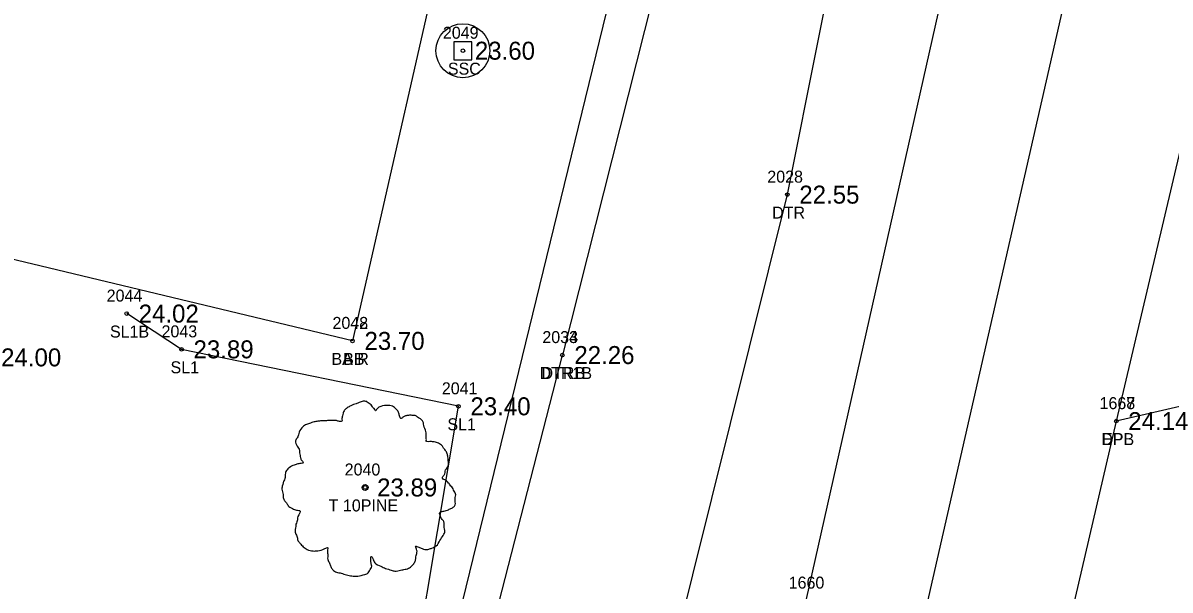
# Model space of a CAD drawing. Extents: x 2654414 to 2656963, y 761776 to 764965.
# Drawn here: x 2655410.2 to 2655506, y 762237.5 to 762284.8 of the extents above; entities that cross this region are included whole.
import ezdxf

# ---------------------------------------------------------------- set-up
doc = ezdxf.new("R2010")
doc.units = 0
for name, color, linetype in [('Default', 7, 'Continuous'), ('RD_EX_Bldg', 7, 'Continuous'), ('RD_EX_Bldg_txCode', 7, 'Continuous'), ('RD_EX_Driveway', 7, 'Continuous'), ('RD_EX_Driveway_txCode', 7, 'Continuous'), ('RD_EX_Fence_Other', 7, 'Continuous'), ('RD_EX_H2O', 7, 'Continuous'), ('RD_EX_H2O_txCode', 7, 'Continuous'), ('RD_EX_Road', 7, 'Continuous'), ('RD_EX_Road_txCode', 7, 'Continuous'), ('RD_EX_TX_Bldg_ELEV', 7, 'Continuous'), ('RD_EX_TX_Conc_ELEV', 7, 'Continuous'), ('RD_EX_TX_Driveway_ELEV', 7, 'Continuous'), ('RD_EX_TX_H2O_ELEV', 7, 'Continuous'), ('RD_EX_TX_Road_ELEV', 7, 'Continuous'), ('RD_EX_TX_UT_ELEV', 7, 'Continuous'), ('RD_EX_TX_VEG_ELEV', 7, 'Continuous'), ('RD_EX_UT', 7, 'Continuous'), ('RD_EX_UT_txCode', 7, 'Continuous'), ('RD_EX_VEG', 7, 'Continuous'), ('RD_EX_VEG_txCode', 7, 'Continuous'), ('RD_HC_Cl', 7, 'Continuous'), ('RD_SMD_Locator', 7, 'Continuous')]:
    doc.layers.add(name, color=color, linetype=linetype)

msp = doc.modelspace()

# ---------------------------------------------------------------- linework, layer by layer
at = {"layer": 'Default'}
msp.add_line((2656050.51, 764712.367), (2655383.263, 761787.511), dxfattribs=at)
at = {"layer": 'RD_EX_Bldg'}
msp.add_lwpolyline([(2655437.715, 762258.295), (2655390.483, 762269.628), (2655398.7, 762307.917), (2655446.539, 762297.096), (2655437.715, 762258.295)], dxfattribs=at)
at = {"layer": 'RD_EX_Driveway'}
msp.add_lwpolyline([(2655508.173, 762280.146), (2655514.751, 762268.051), (2655517.637, 762265.69), (2655514.347, 762252.861), (2655509.918, 762253.548), (2655501.462, 762251.601)], dxfattribs=at)
at = {"layer": 'RD_EX_Fence_Other'}
msp.add_line((2655466.192, 762315.625), (2655445.664, 762231.576), dxfattribs=at)
at = {"layer": 'RD_EX_H2O'}
msp.add_line((2655465.406, 762297.339), (2655455.231, 762257.113), dxfattribs=at)
msp.add_lwpolyline([(2655465.406, 762297.339), (2655472.381, 762299.489), (2655479.157, 762296.474), (2655474.006, 762270.501), (2655462.934, 762226.04), (2655458.028, 762221.446), (2655449.91, 762220.499), (2655446.472, 762222.967), (2655455.231, 762257.113)], dxfattribs=at)
at = {"layer": 'RD_EX_Road'}
for points in [[(2655700.994, 763232.279), (2655693.552, 763198.573), (2655671.649, 763102.037), (2655649.038, 763001.061), (2655627.271, 762906.233), (2655604.996, 762809.365), (2655598.992, 762783.09), (2655583.655, 762714.137), (2655561.97, 762618.323), (2655556.356, 762593.843), (2655548.114, 762557.141), (2655540.102, 762522.478), (2655518.03, 762425.04), (2655496.479, 762329.558), (2655475.552, 762236.625), (2655473.199, 762226.142), (2655466.574, 762197.504), (2655460.058, 762168.164), (2655454.261, 762143.776), (2655432.5, 762049.878), (2655410.7, 761955.515), (2655388.166, 761858.426), (2655373.501, 761793.951)], [(2655670.037, 762995.178), (2655648.569, 762900.673), (2655631.27, 762824.032), (2655626.665, 762802.872), (2655621.781, 762781.907), (2655611.705, 762738.435), (2655604.931, 762708.622), (2655582.644, 762610.543), (2655576.456, 762583.319), (2655561.406, 762517.242), (2655539.154, 762414.805), (2655531.984, 762386.147), (2655517.984, 762324.295), (2655508.173, 762280.146), (2655501.462, 762251.601), (2655496.922, 762232.086), (2655477.204, 762144.974), (2655472.137, 762122.524), (2655453.741, 762045.099), (2655431.791, 761949.924), (2655409.76, 761853.25), (2655401.248, 761816.416), (2655394.612, 761787.366)]]:
    msp.add_lwpolyline(points, dxfattribs=at)
at = {"layer": 'RD_EX_UT'}
for p, q in [((2655447.679, 762283.261), (2655446.178, 762283.262)), ((2655446.178, 762283.262), (2655446.178, 762281.761)), ((2655447.678, 762281.761), (2655447.679, 762283.261)), ((2655446.178, 762281.761), (2655447.678, 762281.761))]:
    msp.add_line(p, q, dxfattribs=at)
msp.add_circle((2655446.928, 762282.511), 2.25, dxfattribs=at)
at = {"layer": 'RD_EX_VEG'}
msp.add_lwpolyline([(2655443.065, 762231.918), (2655446.559, 762252.837), (2655423.447, 762257.591), (2655418.867, 762260.575)], dxfattribs=at)
for centre, radius in [((2655438.769, 762246.065), 0.25), ((2655438.757, 762246.046), 0.0001)]:
    msp.add_circle(centre, radius, dxfattribs=at)
for points in [[(2655438.901, 762253.232), (2655438.601, 762253.257), (2655438.277, 762253.157), (2655438.027, 762253.057), (2655437.802, 762252.982), (2655437.577, 762252.882), (2655437.277, 762252.707), (2655437.052, 762252.507), (2655436.927, 762252.258), (2655436.877, 762252.033), (2655436.827, 762251.758), (2655436.827, 762251.583), (2655436.702, 762251.558), (2655436.552, 762251.583), (2655436.302, 762251.658), (2655436.053, 762251.658), (2655435.803, 762251.658), (2655435.453, 762251.633), (2655435.103, 762251.633), (2655434.828, 762251.583), (2655434.503, 762251.533), (2655434.128, 762251.408), (2655433.779, 762251.283), (2655433.479, 762251.033), (2655433.229, 762250.558), (2655433.104, 762250.208), (2655432.954, 762249.959), (2655433.104, 762249.509), (2655433.279, 762249.159), (2655433.304, 762248.959), (2655433.379, 762248.534), (2655433.479, 762248.309), (2655433.604, 762248.109), (2655433.529, 762248.084), (2655433.154, 762248.034), (2655432.854, 762247.934), (2655432.429, 762247.71), (2655432.204, 762247.485), (2655432.104, 762247.16), (2655432.079, 762246.81), (2655431.979, 762246.61), (2655431.904, 762246.335), (2655431.879, 762246.26), (2655431.829, 762245.935), (2655431.929, 762245.485), (2655431.954, 762245.136), (2655432.079, 762244.911), (2655432.229, 762244.736), (2655432.404, 762244.486), (2655432.804, 762244.261), (2655433.129, 762244.161), (2655433.329, 762244.136), (2655433.154, 762243.636), (2655433.104, 762243.286), (2655432.979, 762242.887), (2655432.979, 762242.812), (2655432.929, 762242.337), (2655433.079, 762242.012), (2655433.154, 762241.637), (2655433.329, 762241.412), (2655433.604, 762241.112), (2655433.928, 762240.888), (2655434.428, 762240.763), (2655434.828, 762240.788), (2655435.403, 762240.962), (2655435.653, 762241.037), (2655435.628, 762240.863), (2655435.653, 762240.488), (2655435.653, 762240.063), (2655435.803, 762239.738), (2655435.903, 762239.463), (2655436.053, 762239.213), (2655436.377, 762238.988), (2655436.777, 762238.913), (2655437.202, 762238.763), (2655437.652, 762238.688), (2655438.152, 762238.663), (2655438.751, 762238.813), (2655439.026, 762238.938), (2655439.126, 762239.113), (2655439.326, 762239.488), (2655439.276, 762239.713), (2655439.301, 762240.313), (2655439.401, 762240.138), (2655439.576, 762239.788), (2655440.076, 762239.488), (2655440.476, 762239.313), (2655440.95, 762239.163), (2655441.25, 762239.088), (2655441.725, 762239.163), (2655442.1, 762239.238), (2655442.475, 762239.363), (2655442.775, 762239.638), (2655442.95, 762239.913), (2655443, 762240.188), (2655443.074, 762240.563), (2655443.124, 762240.738)], [(2655443.124, 762240.738), (2655443.05, 762240.913), (2655443, 762241.162), (2655443.074, 762241.137), (2655443.249, 762241.087), (2655443.524, 762240.962), (2655443.749, 762240.888), (2655444.074, 762240.913), (2655444.349, 762241.012), (2655444.799, 762241.287), (2655445.074, 762241.762), (2655445.348, 762242.162), (2655445.423, 762242.487), (2655445.373, 762242.712), (2655445.348, 762243.211), (2655445.149, 762243.461), (2655445.099, 762243.586), (2655444.999, 762243.986), (2655445.074, 762244.036), (2655445.348, 762244.086), (2655445.723, 762244.211), (2655445.998, 762244.336), (2655446.223, 762244.511), (2655446.298, 762244.736), (2655446.273, 762245.136), (2655446.323, 762245.535), (2655446.248, 762245.685), (2655446.148, 762245.835), (2655446.073, 762246.035), (2655445.923, 762246.185), (2655445.823, 762246.335), (2655445.723, 762246.435), (2655445.598, 762246.585), (2655445.423, 762246.71), (2655445.274, 762246.76), (2655445.224, 762246.91), (2655445.373, 762247.11), (2655445.423, 762247.21), (2655445.448, 762247.435), (2655445.673, 762247.784), (2655445.723, 762248.184), (2655445.673, 762248.609), (2655445.623, 762248.884), (2655445.473, 762249.159), (2655445.274, 762249.409), (2655445.149, 762249.584), (2655444.974, 762249.709), (2655444.649, 762249.834), (2655444.399, 762249.884), (2655444.049, 762249.884), (2655443.849, 762249.934), (2655443.874, 762249.984), (2655443.874, 762250.133), (2655443.874, 762250.408), (2655443.799, 762250.858), (2655443.649, 762251.358), (2655443.649, 762251.383), (2655443.549, 762251.633), (2655443.324, 762251.833), (2655443.149, 762251.933), (2655442.95, 762252.058), (2655442.7, 762252.083), (2655442.4, 762252.083), (2655442.125, 762252.033), (2655441.925, 762251.933), (2655441.75, 762251.808), (2655441.675, 762251.958), (2655441.575, 762252.258), (2655441.525, 762252.407), (2655441.375, 762252.582), (2655441.15, 762252.782), (2655440.7, 762252.907), (2655440.076, 762252.832), (2655439.776, 762252.632), (2655439.626, 762252.457), (2655439.576, 762252.582), (2655439.376, 762252.782), (2655439.276, 762252.957), (2655439.101, 762253.082), (2655438.951, 762253.182), (2655438.851, 762253.232)]]:
    msp.add_spline(points, degree=3, dxfattribs=at)
at = {"layer": 'RD_HC_Cl'}
msp.add_line((2656050.51, 764712.367), (2655383.263, 761787.511), dxfattribs=at)
at = {"layer": 'RD_SMD_Locator'}
for centre in [(2655446.928, 762282.511), (2655474.006, 762270.501), (2655418.867, 762260.575), (2655437.715, 762258.295), (2655437.715, 762258.295), (2655423.447, 762257.591), (2655455.231, 762257.113), (2655455.231, 762257.113), (2655446.559, 762252.837), (2655501.462, 762251.601), (2655501.462, 762251.601), (2655438.769, 762246.065)]:
    msp.add_circle(centre, 0.15, dxfattribs=at)

# ---------------------------------------------------------------- texts
at = {"layer": 'RD_EX_Bldg_txCode'}
for s, p in [('2042', (2655436.046, 762259.295)), ('2048', (2655436.046, 762259.295)), ('BA R', (2655435.959, 762256.295)), ('BB', (2655436.936, 762256.295))]:
    msp.add_text(s, height=1, dxfattribs=at).set_placement(p)
at = {"layer": 'RD_EX_Driveway_txCode'}
for s, p in [('1667', (2655500.068, 762252.601)), ('DPB', (2655500.21, 762249.601))]:
    msp.add_text(s, height=1, dxfattribs=at).set_placement(p)
at = {"layer": 'RD_EX_H2O_txCode'}
for s, p in [('2028', (2655472.337, 762271.501)), ('DTR', (2655472.738, 762268.501)), ('2033', (2655453.561, 762258.113)), ('2034', (2655453.561, 762258.113)), ('DTR1B', (2655453.325, 762255.113)), ('DTRB', (2655453.491, 762255.113))]:
    msp.add_text(s, height=1, dxfattribs=at).set_placement(p)
at = {"layer": 'RD_EX_Road_txCode'}
for s, p in [('1668', (2655500.068, 762252.601)), ('EPL', (2655500.257, 762249.601)), ('1660', (2655474.119, 762237.625))]:
    msp.add_text(s, height=1, dxfattribs=at).set_placement(p)
at = {"layer": 'RD_EX_TX_Bldg_ELEV'}
msp.add_text('23.70', height=1.5, dxfattribs=at).set_placement((2655438.715, 762257.545))
msp.add_text('23.70', height=1.5, dxfattribs=at).set_placement((2655438.715, 762257.545))
at = {"layer": 'RD_EX_TX_Conc_ELEV'}
msp.add_text('24.00', height=1.5, dxfattribs=at).set_placement((2655408.386, 762256.169))
at = {"layer": 'RD_EX_TX_Driveway_ELEV'}
msp.add_text('24.14', height=1.5, dxfattribs=at).set_placement((2655502.462, 762250.851))
at = {"layer": 'RD_EX_TX_H2O_ELEV'}
for s, p in [('22.55', (2655475.006, 762269.751)), ('22.26', (2655456.231, 762256.363)), ('22.26', (2655456.231, 762256.363))]:
    msp.add_text(s, height=1.5, dxfattribs=at).set_placement(p)
at = {"layer": 'RD_EX_TX_Road_ELEV'}
msp.add_text('24.14', height=1.5, dxfattribs=at).set_placement((2655502.462, 762250.851))
at = {"layer": 'RD_EX_TX_UT_ELEV'}
msp.add_text('23.60', height=1.5, dxfattribs=at).set_placement((2655447.928, 762281.761))
at = {"layer": 'RD_EX_TX_VEG_ELEV'}
for s, p in [('24.02', (2655419.867, 762259.825)), ('23.89', (2655424.447, 762256.841)), ('23.40', (2655447.559, 762252.087)), ('23.89', (2655439.769, 762245.315))]:
    msp.add_text(s, height=1.5, dxfattribs=at).set_placement(p)
at = {"layer": 'RD_EX_UT_txCode'}
for s, p in [('2049', (2655445.259, 762283.511)), ('SSC', (2655445.676, 762280.511))]:
    msp.add_text(s, height=1, dxfattribs=at).set_placement(p)
at = {"layer": 'RD_EX_VEG_txCode'}
for s, p in [('2044', (2655417.198, 762261.575)), ('SL1B', (2655417.473, 762258.575)), ('2043', (2655421.777, 762258.591)), ('SL1', (2655422.525, 762255.591)), ('2041', (2655445.173, 762253.837)), ('SL1', (2655445.638, 762250.837)), ('2040', (2655437.061, 762247.065)), ('T 10PINE', (2655435.726, 762244.065))]:
    msp.add_text(s, height=1, dxfattribs=at).set_placement(p)

doc.saveas('drawing.dxf')
